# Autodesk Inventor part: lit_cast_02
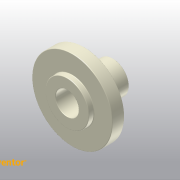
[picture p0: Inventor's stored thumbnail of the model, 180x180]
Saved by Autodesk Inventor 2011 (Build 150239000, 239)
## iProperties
Shininess: 64.0
Length Units: 11269
Angle Units: 11279
Time Units: 11290
Mass Units: 11283
Length Display Precision: 3
Angle Display Precision: 2
Compacted: True
Company: Autodesk
Created: 2002-07
Part Number: lit_cast_02
Document SubType Name: Modeling
Designer: Lieven Grauls
Stock Number: lit_cast_02
Project: Valve Techcamp 2008
Density: 1 g/cm^3
Density: 0.0
Volumn: 0.0
Area: 0.0
PropertySet Name: Model Information
Control State: 0
Master: False
Checked Out: False
Author: Lieven Grauls
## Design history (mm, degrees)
sketch "Sketch1"
  geometry: L1 (20, 0)-(38, 0); L2 (38, 0)-(38, 9); L3 (38, 9)-(70, 9); L4 (70, 9)-(70, 30); L5 (70, 30)-(35, 30); L6 (35, 30)-(35, 53); L7 (35, 53)-(28, 53); L8 (28, 53)-(28, 80); L9 (28, 80)-(10, 80); L10 (10, 80)-(10, 60); L11 (10, 60)-(6.75, 60); L12 (6.75, 60)-(6.75, 45); L13 (6.75, 45)-(20, 45); L14 (20, 45)-(20, 0); L15 (0, -16)-(0, 96) reference; 1 further point
  constraints: 28 end point, 10 parallel, 3 perpendicular, 1 horizontal, 1 horizontal alignment
  dimensions: "d0" = 13.5 diameter of L12 L15; "d1" = 20 diameter of L10 L15; "d2" = 56 diameter of L8 L15; "d3" = 70 diameter of L6 L15; "d4" = 40 diameter of L14 L15; "d5" = 76 diameter of L2 L15; "d6" = 140 diameter of L4 L15; "d7" = 9 distance between parallel lines of L3 L1; "d8" = 80 distance between parallel lines of L1 L9; "d9" = 27 distance between parallel lines of L7 L9; "d10" = 20 distance between parallel lines of L9 L11; "d11" = 45 distance between parallel lines of L1 L13; "d12" = 30 distance between parallel lines of L1 L5
revolve "Revolution1" sketch "Sketch1" stored, may be unused: angle "d13" = 90 deg
fillet "Fillet1" dims "d14" = 10, "d15" = 5
fillet "Fillet2" dims "d16" = 1
node "Volumenkörper1"
node "Volumenkörpern"
node "Oberflächenkörpern"
